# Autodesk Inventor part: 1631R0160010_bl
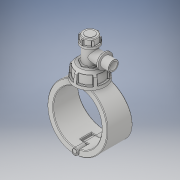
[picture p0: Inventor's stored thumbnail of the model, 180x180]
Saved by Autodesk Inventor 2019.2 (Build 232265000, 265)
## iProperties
Created: 2022-02
Part Number: 1631R0160010_bl
Material: Generic
Description: Plassadle Tapper Male 160x1''
Document SubType Name: Modeling
Designer: comp2
Density: 1 g/cm^3
Appearance: Default
Author: comp2
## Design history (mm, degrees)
derived "1631R.ipt"
feature "Solid1::1631R.ipt" dims "ScaleForDerivedMember" = 10
feature "Solid2::1631R.ipt" dims "ScaleForDerivedMember" = 10
feature "Solid3::1631R.ipt" dims "ScaleForDerivedMember" = 10
feature "Solid4::1631R.ipt" dims "ScaleForDerivedMember" = 10
tag "TaggingFeature1"
body "Solid1"
body "Solid2"
body "Solid3"
body "Solid4"
other parameters: "d2" = 198 [user parameter], "d5" = 325 [user parameter], "d7" = 188.1 [user parameter], "d8" = 85 deg [user parameter], "d9" = 45 deg [user parameter], "d10" = 102 [user parameter], "d11" = 49 [user parameter], "d12" = 34.3 [user parameter], "d13" = 42.84 [user parameter], "d14" = 57.936 [user parameter], "d15" = 2.45 [user parameter], "d16" = 2 [user parameter], "d17" = 2 [user parameter], "d18" = 29.4 [user parameter], "d19" = 7.35 [user parameter], "d20" = 1 [user parameter], "d21" = 30.6 [user parameter], "d22" = 1 [user parameter], "d23" = 14.7 [user parameter], "d24" = 78 [user parameter], "d27" = 144 [user parameter], "d29" = 49.8735 [user parameter], "d31" = 33.249 [user parameter], "d32" = 31.2 [user parameter], "d33" = 26.52 [user parameter], "d41" = 5 [user parameter], "d42" = 3.8 [user parameter], "d46" = 56.1 [user parameter], "d47" = 36.5739 [user parameter], "d48" = 49 [user parameter], "d49" = 3.96 [user parameter], "d50" = 106 [user parameter], "d51" = 0 [user parameter], "d52" = 26.6 [user parameter], "d53" = 108.9 [user parameter], "d54" = 37.1 [user parameter], "d55" = 0 [user parameter], "d56" = 21.2 [user parameter], "d57" = 21.2 [user parameter], "d59" = 0 [user parameter], "d60" = 106 [user parameter], "d61" = 0 [user parameter], "d62" = 37.1 [user parameter], "d63" = 0 [user parameter], "d65" = 0 [user parameter], "d67" = 0 [user parameter], "d69" = 0 [user parameter], "d70" = 1 [user parameter], "d71" = 101.76 [user parameter], "d72" = 0 [user parameter], "d73" = 2 [user parameter], "d77" = 24.93675 [user parameter], "d78" = 86.7 [user parameter], "d79" = 5.1 [user parameter], "d80" = 60 deg [user parameter], "d81" = 5.1 [user parameter], "d84" = 0 [user parameter], "d85" = 1 [user parameter], "d87" = 360 deg [user parameter], "d90" = 0 [user parameter], "d91" = 1 [user parameter], "d93" = 60 deg [user parameter], "d94" = 3.06 [user parameter], "d95" = 3.06 [user parameter], "d97" = 0 [user parameter], "d98" = 0.5 [user parameter], "d100" = 360 deg [user parameter], "d102" = 2 [user parameter], "d117" = 0.5 [user parameter], "d118" = 31.2 [user parameter], "d119" = 100 deg [user parameter], "d121" = 0 [user parameter], "d1" = 25 [user parameter], "B" = 198 [user parameter], "L" = 106 [user parameter], "E_" = 54 [user parameter], "E1" = 102 [user parameter], "H1" = 325 [user parameter], "H2" = 144 [user parameter], "H3" = 78 [user parameter], "H_costum" = 49 [user parameter], "R" = 33.249 [user parameter]
